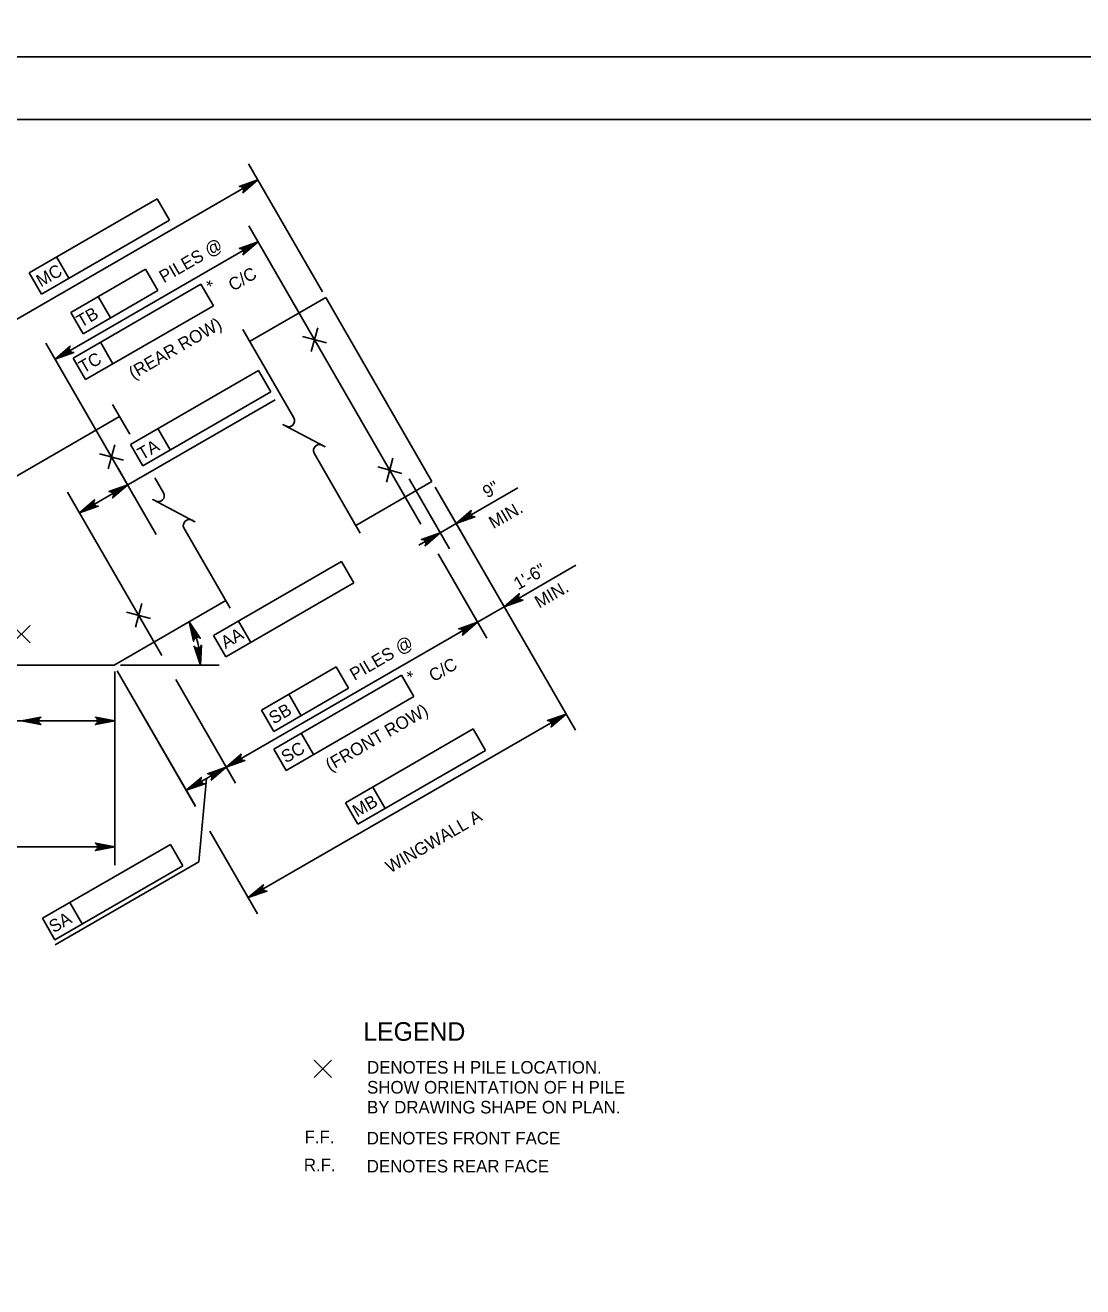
# Model space of a CAD drawing. Extents: x 638340 to 640242, y 295465 to 298435.
# Drawn here: x 639648.4 to 639900.6, y 295766.2 to 296067 of the extents above; entities that cross this region are included whole.
import ezdxf

# ---------------------------------------------------------------- set-up
doc = ezdxf.new("R2010")
doc.units = 0
for name, color, linetype in [('2', 7, 'Continuous'), ('4', 7, 'Continuous'), ('Level 2', 7, 'Continuous'), ('Level 3', 7, 'Continuous'), ('Level 4', 7, 'Continuous'), ('PLT-BNDY', 7, 'Continuous')]:
    doc.layers.add(name, color=color, linetype=linetype)

# ---------------------------------------------------------------- blocks, each defined once
blk = doc.blocks.new('PILE')
at = {"layer": '2'}
for p, q in [((-2.651625, -2.651625), (2.651625, 2.651625)), ((-2.651625, 2.651625), (2.651625, -2.651625))]:
    blk.add_line(p, q, dxfattribs=at)

msp = doc.modelspace()

# ---------------------------------------------------------------- linework, layer by layer
at = {"layer": '2'}
msp.add_line((639316.46, 296044.46), (640102.46, 296044.46), dxfattribs=at)
at = {"layer": 'Level 2'}
for p, q in [((639719.28, 296003.39), (639701.66, 296033.91)), ((639629.17, 295986.95), (639703.87, 296030.08)), ((639649.29, 296007.95), (639679.8, 296025.56)), ((639679.8, 296025.56), (639682.75, 296020.46)), ((639652.24, 296002.84), (639682.75, 296020.46)), ((639701.68, 296019.14), (639742.73, 295948.03)), ((639703.89, 296015.31), (639655.48, 295987.36)), ((639655.82, 296011.72), (639658.77, 296006.62)), ((639649.29, 296007.95), (639652.24, 296002.84)), ((639659.22, 295998.5), (639677.06, 296008.8)), ((639677.06, 296008.8), (639680.01, 296003.69)), ((639659.77, 295987.6), (639690.29, 296005.21)), ((639690.29, 296005.21), (639693.24, 296000.1)), ((639662.17, 295993.39), (639680.01, 296003.69)), ((639665.76, 296002.27), (639668.7, 295997.16)), ((639659.22, 295998.5), (639662.17, 295993.39)), ((639662.72, 295982.5), (639693.24, 296000.1)), ((639679.61, 295945.56), (639653.27, 295991.19)), ((639666.31, 295991.38), (639669.26, 295986.27)), ((639659.77, 295987.6), (639662.72, 295982.5)), ((639673.48, 295967.03), (639704, 295984.63)), ((639704, 295984.63), (639706.94, 295979.53)), ((639672.81, 295957.35), (639708.02, 295977.67)), ((639676.42, 295961.92), (639706.94, 295979.53)), ((639680.01, 295970.8), (639682.96, 295965.7)), ((639673.48, 295967.03), (639676.42, 295961.92)), ((639674.31, 295954.76), (639670.6, 295961.18)), ((639661.3, 295950.7), (639672.81, 295957.35)), ((639739.92, 295958.79), (639749.54, 295942.14)), ((639746.14, 295956.86), (639753.37, 295944.35)), ((639746.14, 295956.86), (639764.82, 295924.51)), ((639746.14, 295956.86), (639779.6, 295898.92)), ((639751.16, 295948.18), (639765.86, 295956.66)), ((639658.44, 295955.67), (639680.92, 295916.73)), ((639747.33, 295945.96), (639751.16, 295948.18)), ((639747.33, 295945.96), (639742.22, 295943.02)), ((639693.29, 295921.46), (639723.79, 295939.1)), ((639723.79, 295939.1), (639726.74, 295934)), ((639746.83, 295940.94), (639758.44, 295920.83)), ((639762.61, 295928.34), (639779.69, 295938.2)), ((639726.74, 295934), (639696.24, 295916.35)), ((639756.23, 295924.66), (639762.61, 295928.34)), ((639756.23, 295924.66), (639696.31, 295890.07)), ((639702.16, 295919.78), (639699.21, 295924.88)), ((639753.68, 295923.18), (639751.12, 295921.71)), ((639696.24, 295916.35), (639693.29, 295921.46)), ((639671.09, 295914.41), (639694.62, 295914.41)), ((639704.69, 295903.66), (639722.52, 295913.99)), ((639722.52, 295913.99), (639725.47, 295908.9)), ((639669.75, 295912.88), (639669.75, 295866.68)), ((639670.32, 295913.08), (639689, 295880.74)), ((639670.32, 295913.08), (639688.88, 295880.95)), ((639684.26, 295910.94), (639698.52, 295886.24)), ((639707.63, 295894.39), (639738.12, 295912.05)), ((639738.12, 295912.05), (639741.07, 295906.95)), ((639707.65, 295898.56), (639725.47, 295908.9)), ((639710.58, 295889.29), (639741.07, 295906.95)), ((639711.22, 295907.45), (639714.18, 295902.35)), ((639701.57, 295858.97), (639777.39, 295902.75)), ((639704.69, 295903.66), (639707.65, 295898.56)), ((639669.75, 295901.09), (639606.61, 295901.09)), ((639724.72, 295881.57), (639755.23, 295899.19)), ((639755.23, 295899.19), (639758.18, 295894.08)), ((639714.16, 295898.18), (639717.11, 295893.08)), ((639707.63, 295894.39), (639710.58, 295889.29)), ((639727.67, 295876.47), (639758.18, 295894.08)), ((639696.31, 295890.07), (639686.79, 295884.57)), ((639691.6, 295887.34), (639689.78, 295867.52)), ((639731.26, 295885.35), (639734.2, 295880.24)), ((639724.72, 295881.57), (639727.67, 295876.47)), ((639692.41, 295874.82), (639703.78, 295855.14)), ((639510.35, 295871.1), (639669.75, 295871.1)), ((639652.46, 295854.05), (639682.98, 295871.65)), ((639682.98, 295871.65), (639685.93, 295866.55)), ((639655.41, 295848.94), (639685.93, 295866.55)), ((639689.78, 295867.52), (639655.49, 295847.72)), ((639658.99, 295857.82), (639661.94, 295852.72)), ((639652.46, 295854.05), (639655.41, 295848.94))]:
    msp.add_line(p, q, dxfattribs=at)
for points in [[(639703.87, 296030.08), (639700.28, 296027), (639700.46, 296027.39), (639700.47, 296027.76), (639700.36, 296028.05), (639700.16, 296028.3), (639699.84, 296028.48), (639699.41, 296028.51), (639703.87, 296030.08), (639699.84, 296028.48), (639700.16, 296028.3), (639703.87, 296030.08), (639700.36, 296028.05), (639700.47, 296027.76), (639703.87, 296030.08), (639700.46, 296027.39)], [(639703.89, 296015.31), (639700.3, 296012.23), (639700.48, 296012.63), (639700.49, 296012.99), (639700.38, 296013.29), (639700.18, 296013.53), (639699.86, 296013.71), (639699.42, 296013.74), (639703.89, 296015.31), (639699.86, 296013.71), (639700.18, 296013.53), (639703.89, 296015.31), (639700.38, 296013.29), (639700.49, 296012.99), (639703.89, 296015.31), (639700.48, 296012.63)], [(639655.48, 295987.36), (639659.07, 295990.45), (639658.89, 295990.05), (639658.88, 295989.69), (639658.99, 295989.39), (639659.19, 295989.15), (639659.51, 295988.97), (639659.94, 295988.93), (639655.48, 295987.36), (639659.51, 295988.97), (639659.19, 295989.15), (639655.48, 295987.36), (639658.99, 295989.39), (639658.88, 295989.69), (639655.48, 295987.36), (639658.89, 295990.05)], [(639672.81, 295957.35), (639669.22, 295954.27), (639669.4, 295954.66), (639669.41, 295955.02), (639669.3, 295955.32), (639669.1, 295955.56), (639668.78, 295955.74), (639668.34, 295955.78), (639672.81, 295957.35), (639668.78, 295955.74), (639669.1, 295955.56), (639672.81, 295957.35), (639669.3, 295955.32), (639669.41, 295955.02), (639672.81, 295957.35), (639669.4, 295954.66)], [(639661.3, 295950.7), (639664.9, 295953.79), (639664.71, 295953.39), (639664.71, 295953.03), (639664.82, 295952.73), (639665.02, 295952.49), (639665.33, 295952.31), (639665.77, 295952.27), (639661.3, 295950.7), (639665.33, 295952.31), (639665.02, 295952.49), (639661.3, 295950.7), (639664.82, 295952.73), (639664.71, 295953.03), (639661.3, 295950.7), (639664.71, 295953.39)], [(639751.16, 295948.18), (639754.75, 295951.26), (639754.56, 295950.86), (639754.56, 295950.5), (639754.67, 295950.2), (639754.87, 295949.96), (639755.19, 295949.78), (639755.62, 295949.75), (639751.16, 295948.18), (639755.19, 295949.78), (639754.87, 295949.96), (639751.16, 295948.18), (639754.67, 295950.2), (639754.56, 295950.5), (639751.16, 295948.18), (639754.56, 295950.86)], [(639747.33, 295945.96), (639743.74, 295942.88), (639743.92, 295943.28), (639743.93, 295943.64), (639743.82, 295943.94), (639743.62, 295944.18), (639743.3, 295944.36), (639742.87, 295944.39), (639747.33, 295945.96), (639743.3, 295944.36), (639743.62, 295944.18), (639747.33, 295945.96), (639743.82, 295943.94), (639743.93, 295943.64), (639747.33, 295945.96), (639743.92, 295943.28)], [(639762.61, 295928.34), (639766.2, 295931.42), (639766.02, 295931.03), (639766.01, 295930.66), (639766.12, 295930.37), (639766.32, 295930.12), (639766.64, 295929.95), (639767.08, 295929.91), (639762.61, 295928.34), (639766.64, 295929.95), (639766.32, 295930.12), (639762.61, 295928.34), (639766.12, 295930.37), (639766.01, 295930.66), (639762.61, 295928.34), (639766.02, 295931.03)], [(639687.44, 295924.71), (639690.11, 295920.81), (639689.74, 295921.04), (639689.38, 295921.08), (639689.07, 295921), (639688.81, 295920.83), (639688.6, 295920.53), (639688.51, 295920.1), (639687.44, 295924.71), (639688.6, 295920.53), (639688.81, 295920.83), (639687.44, 295924.71), (639689.07, 295921), (639689.38, 295921.08), (639687.44, 295924.71), (639689.74, 295921.04)], [(639756.23, 295924.66), (639752.64, 295921.57), (639752.82, 295921.97), (639752.83, 295922.33), (639752.72, 295922.63), (639752.52, 295922.87), (639752.2, 295923.05), (639751.76, 295923.09), (639756.23, 295924.66), (639752.2, 295923.05), (639752.52, 295922.87), (639756.23, 295924.66), (639752.72, 295922.63), (639752.83, 295922.33), (639756.23, 295924.66), (639752.82, 295921.97)], [(639690.19, 295914.42), (639688.66, 295918.9), (639688.96, 295918.58), (639689.29, 295918.44), (639689.61, 295918.44), (639689.91, 295918.53), (639690.19, 295918.76), (639690.39, 295919.15), (639690.19, 295914.42), (639690.19, 295918.76), (639689.91, 295918.53), (639690.19, 295914.42), (639689.61, 295918.44), (639689.29, 295918.44), (639690.19, 295914.42), (639688.96, 295918.58)], [(639647.45, 295901.09), (639652.1, 295901.96), (639651.75, 295901.72), (639651.56, 295901.4), (639651.51, 295901.09), (639651.56, 295900.78), (639651.75, 295900.47), (639652.1, 295900.22), (639647.45, 295901.09), (639651.75, 295900.47), (639651.56, 295900.78), (639647.45, 295901.09), (639651.51, 295901.09), (639651.56, 295901.4), (639647.45, 295901.09), (639651.75, 295901.72)], [(639669.75, 295901.09), (639665.1, 295900.22), (639665.46, 295900.47), (639665.64, 295900.78), (639665.7, 295901.09), (639665.64, 295901.4), (639665.46, 295901.72), (639665.1, 295901.96), (639669.75, 295901.09), (639665.46, 295901.72), (639665.64, 295901.4), (639669.75, 295901.09), (639665.7, 295901.09), (639665.64, 295900.78), (639669.75, 295901.09), (639665.46, 295900.47)], [(639777.39, 295902.75), (639773.79, 295899.66), (639773.98, 295900.06), (639773.98, 295900.42), (639773.87, 295900.72), (639773.67, 295900.96), (639773.36, 295901.14), (639772.92, 295901.18), (639777.39, 295902.75), (639773.36, 295901.14), (639773.67, 295900.96), (639777.39, 295902.75), (639773.87, 295900.72), (639773.98, 295900.42), (639777.39, 295902.75), (639773.98, 295900.06)], [(639696.31, 295890.07), (639699.91, 295893.15), (639699.72, 295892.75), (639699.72, 295892.39), (639699.83, 295892.09), (639700.03, 295891.85), (639700.34, 295891.67), (639700.78, 295891.64), (639696.31, 295890.07), (639700.34, 295891.67), (639700.03, 295891.85), (639696.31, 295890.07), (639699.83, 295892.09), (639699.72, 295892.39), (639696.31, 295890.07), (639699.72, 295892.75)], [(639696.31, 295890.07), (639692.72, 295886.98), (639692.91, 295887.38), (639692.91, 295887.74), (639692.8, 295888.04), (639692.6, 295888.28), (639692.28, 295888.46), (639691.85, 295888.5), (639696.31, 295890.07), (639692.28, 295888.46), (639692.6, 295888.28), (639696.31, 295890.07), (639692.8, 295888.04), (639692.91, 295887.74), (639696.31, 295890.07), (639692.91, 295887.38)], [(639686.79, 295884.57), (639690.38, 295887.65), (639690.19, 295887.25), (639690.19, 295886.89), (639690.3, 295886.59), (639690.5, 295886.35), (639690.82, 295886.17), (639691.25, 295886.14), (639686.79, 295884.57), (639690.82, 295886.17), (639690.5, 295886.35), (639686.79, 295884.57), (639690.3, 295886.59), (639690.19, 295886.89), (639686.79, 295884.57), (639690.19, 295887.25)], [(639669.75, 295871.1), (639665.1, 295870.23), (639665.46, 295870.48), (639665.64, 295870.79), (639665.7, 295871.1), (639665.64, 295871.41), (639665.46, 295871.73), (639665.1, 295871.97), (639669.75, 295871.1), (639665.46, 295871.73), (639665.64, 295871.41), (639669.75, 295871.1), (639665.7, 295871.1), (639665.64, 295870.79), (639669.75, 295871.1), (639665.46, 295870.48)], [(639701.57, 295858.97), (639705.16, 295862.05), (639704.97, 295861.65), (639704.97, 295861.29), (639705.08, 295861), (639705.28, 295860.75), (639705.6, 295860.58), (639706.03, 295860.54), (639701.57, 295858.97), (639705.6, 295860.58), (639705.28, 295860.75), (639701.57, 295858.97), (639705.08, 295861), (639704.97, 295861.29), (639701.57, 295858.97), (639704.97, 295861.65)]]:
    msp.add_lwpolyline(points, dxfattribs=at)
for points in [[(639701.07, 296029.03), (639701.56, 296028.18), (639703.87, 296030.08)], [(639701.09, 296014.26), (639701.58, 296013.41), (639703.89, 296015.31)], [(639657.79, 295989.26), (639658.28, 295988.41), (639655.48, 295987.36)], [(639670.01, 295956.3), (639670.5, 295955.45), (639672.81, 295957.35)], [(639663.61, 295952.6), (639664.1, 295951.75), (639661.3, 295950.7)], [(639753.47, 295950.08), (639753.96, 295949.22), (639751.16, 295948.18)], [(639744.53, 295944.92), (639745.02, 295944.07), (639747.33, 295945.96)], [(639764.92, 295930.24), (639765.41, 295929.39), (639762.61, 295928.34)], [(639753.43, 295923.61), (639753.92, 295922.76), (639756.23, 295924.66)], [(639753.43, 295923.61), (639753.92, 295922.76), (639756.23, 295924.66)], [(639774.59, 295901.7), (639775.08, 295900.84), (639777.39, 295902.75)], [(639650.4, 295901.58), (639650.4, 295900.6), (639647.45, 295901.09)], [(639666.61, 295901.58), (639666.61, 295900.6), (639669.56, 295901.09)], [(639693.52, 295889.02), (639694.01, 295888.16), (639696.31, 295890.07)], [(639698.62, 295891.96), (639699.11, 295891.11), (639696.31, 295890.07)], [(639689.1, 295886.46), (639689.59, 295885.61), (639686.79, 295884.57)], [(639666.8, 295871.59), (639666.8, 295870.61), (639669.75, 295871.1)], [(639703.87, 295860.87), (639704.37, 295860.02), (639701.57, 295858.97)]]:
    msp.add_lwpolyline(points, close=True, dxfattribs=at)
msp.add_arc((639669.56, 295914.41), 20.64, 359.9703, 29.9903, dxfattribs=at)
at = {"layer": 'Level 3'}
for p, q in [((639701.89, 295991.57), (639720.05, 296002.06)), ((639745.38, 295958.19), (639720.05, 296002.06)), ((639645.35, 295958.93), (639670.87, 295973.66)), ((639727.22, 295947.7), (639745.38, 295958.19)), ((639669.56, 295914.41), (639696.2, 295929.8)), ((639603.57, 295914.41), (639669.56, 295914.41))]:
    msp.add_line(p, q, dxfattribs=at)
at = {"layer": 'Level 4'}
for p, q in [((639700.24, 295994.43), (639712.4, 295973.36)), ((639669.2, 295976.57), (639673.31, 295969.44)), ((639717.25, 295964.96), (639728.29, 295945.85)), ((639679.31, 295959.05), (639681.36, 295955.5)), ((639686.21, 295947.1), (639697.24, 295927.99))]:
    msp.add_line(p, q, dxfattribs=at)
for points in [[(639710.47, 295971.42), (639709.84, 295971.76), (639719.88, 295966.45), (639719.2, 295966.81)], [(639679.42, 295953.56), (639678.8, 295953.89), (639688.83, 295948.59), (639688.16, 295948.95)]]:
    msp.add_lwpolyline(points, dxfattribs=at)
for centre, start, end in [((639711.18, 295972.65), 240, 30), ((639718.54, 295965.56), 62.1328, 204.6714), ((639680.13, 295954.79), 240, 30), ((639687.49, 295947.69), 62.1328, 204.6714)]:
    msp.add_arc(centre, 1.42, start, end, dxfattribs=at)
at = {"layer": 'PLT-BNDY'}
for points in [[(639276.46, 296653.46), (640117.46, 296653.46), (640117.46, 296059.46), (639276.46, 296059.46)], [(639276.46, 296059.46), (640117.46, 296059.46), (640117.46, 295465.46), (639276.46, 295465.46)]]:
    msp.add_lwpolyline(points, close=True, dxfattribs=at)

# ---------------------------------------------------------------- block references
at = {"layer": 'Level 2', "xscale": 0.7859001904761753, "yscale": -0.7859001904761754, "rotation": -149.99999999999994}
for p in [(639717.36, 295991.99), (639668.95, 295964.04), (639735.31, 295960.89), (639675.4, 295926.29)]:
    msp.add_blockref('PILE', p, dxfattribs=at)
at = {"layer": 'Level 2', "xscale": 0.7859001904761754, "yscale": 0.7859001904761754}
for p in [(639647.46, 295921.78), (639719.33, 295818.17)]:
    msp.add_blockref('PILE', p, dxfattribs=at)

# ---------------------------------------------------------------- texts
at = {"layer": '4'}
msp.add_text('LEGEND', height=4.429, dxfattribs=at).set_placement((639728.99, 295824.85))
at = {"layer": 'Level 2'}
for s, height, rotation, p in [('PILES @', 3, 30, (639681.42, 296005.43)), ('MC', 3, 29.9382, (639652.1, 296004.44)), ('C/C', 3, 29.9382, (639697.92, 296003.43)), ('*', 3, 59.9382, (639693.8, 296003.63)), ('TB', 3, 29.9382, (639661.7, 295994.8)), ('(REAR ROW)', 3, 30, (639674.16, 295982.47)), ('TC', 3, 29.9382, (639662.25, 295983.9)), ('TA', 3, 29.9382, (639676.26, 295963.2)), ('9"', 3, 30, (639758.56, 295954.09)), ('MIN.', 3, 30, (639760.04, 295946.79)), ('1\'-6"', 3, 30, (639765.95, 295932.23)), ('MIN.', 3, 30, (639770.97, 295927.87)), ('AA', 3, 30.0491, (639696.13, 295918.22)), ('PILES @', 3, 30.0982, (639726.88, 295910.64)), ('C/C', 3, 30.0364, (639745.74, 295910.29)), ('*', 3, 60.0364, (639741.62, 295910.47)), ('SB', 3, 30.0364, (639707.59, 295900.21)), ('(FRONT ROW)', 3.0001, 30.0982, (639721.09, 295889)), ('SC', 3, 30.0364, (639710.53, 295890.94)), ('MB', 3, 29.9382, (639727.53, 295878.06)), ('WINGWALL A', 3, 30, (639735.42, 295864.72)), ('SA', 3, 29.9382, (639655.13, 295850.46))]:
    msp.add_text(s, height=height, rotation=rotation, dxfattribs=at).set_placement(p)
for s, p in [('DENOTES H PILE LOCATION.', (639729.9, 295817.02)), ('SHOW ORIENTATION OF H PILE', (639729.9, 295812.27)), ('BY DRAWING SHAPE ON PLAN.', (639729.9, 295807.52))]:
    msp.add_text(s, height=3.0001, dxfattribs=at).set_placement(p)
at = {"layer": 'Level 4'}
for s, height, p in [('F.F.', 3, (639714.99, 295800.43)), ('DENOTES FRONT FACE', 3.0001, (639729.83, 295800.14)), ('R.F.', 3, (639714.82, 295793.75)), ('DENOTES REAR FACE', 3.0001, (639729.83, 295793.46))]:
    msp.add_text(s, height=height, dxfattribs=at).set_placement(p)

doc.saveas('drawing.dxf')
